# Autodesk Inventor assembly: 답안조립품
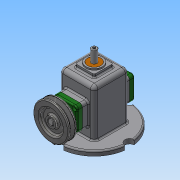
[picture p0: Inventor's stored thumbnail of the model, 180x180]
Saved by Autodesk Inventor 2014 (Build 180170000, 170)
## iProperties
Created: 2018-07
Part Number: 답안조립품
Document SubType Name: Assembly
Designer: 학생용
Author: 학생용
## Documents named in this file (14)
- C:\Users\학생용\Desktop\480707V1021\답안조립품.iam
- C:\Users\학생용\Desktop\480707V1021\답안도면.ipt
- C:\Users\학생용\Desktop\480707V1021\편심축.ipt
- C:\Users\학생용\Desktop\480707V1021\키 4x4x10.ipt
- C:\Users\학생용\Desktop\480707V1021\베어링 12x32x10.ipt
- C:\Users\학생용\Desktop\480707V1021\앞커버.ipt
- C:\Users\학생용\Desktop\480707V1021\링크.ipt
- C:\Users\학생용\Desktop\480707V1021\뒤커버.ipt
- C:\Users\학생용\Desktop\480707V1021\슬라이드.ipt
- C:\Users\학생용\Desktop\480707V1021\오일 실 12 25 7.ipt
- C:\Users\학생용\Desktop\480707V1021\V벨트풀리.ipt
- C:\Users\학생용\Desktop\480707V1021\부시.ipt
- C:\Users\학생용\Desktop\480707V1021\핀 5x18.ipt
- C:\Users\학생용\Desktop\480707V1021\고정핀 1.2x8.ipt
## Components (3 placed, 3 different names)
1. V벨트풀리:1
2. 핀 5x18:1 — 플러쉬:1
3. 고정핀 1.2x8:1 — 플러쉬:1
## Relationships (1: Flush 1)
- 플러쉬:1 [Flush]: 핀 5x18:1 ↔ 고정핀 1.2x8:1
